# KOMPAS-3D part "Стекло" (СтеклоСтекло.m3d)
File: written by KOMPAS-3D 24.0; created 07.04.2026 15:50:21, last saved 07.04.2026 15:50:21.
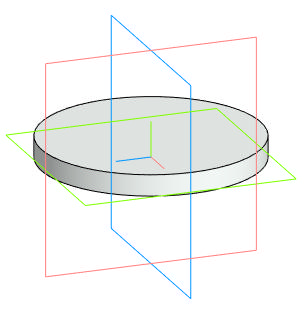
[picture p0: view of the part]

Document properties: Автор: Main; Полное имя файла: D:\DN.ru Аутсерс\Стекло смотровое DN.ru\Исходники\Стекло смотровое DN.ru SG2-34G-F тип В ГОСТ 21836-2021 Ду25 Ру40, углеродистая сталь, фланцевое\СтеклоСтекло.m3d

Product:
- Body: Твердое тело1  | qty 1
- Part/product: Стекло

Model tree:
1. Твердое тело1  (labels: Твердое тело1)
